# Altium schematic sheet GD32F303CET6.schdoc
size 127 x 101 mm
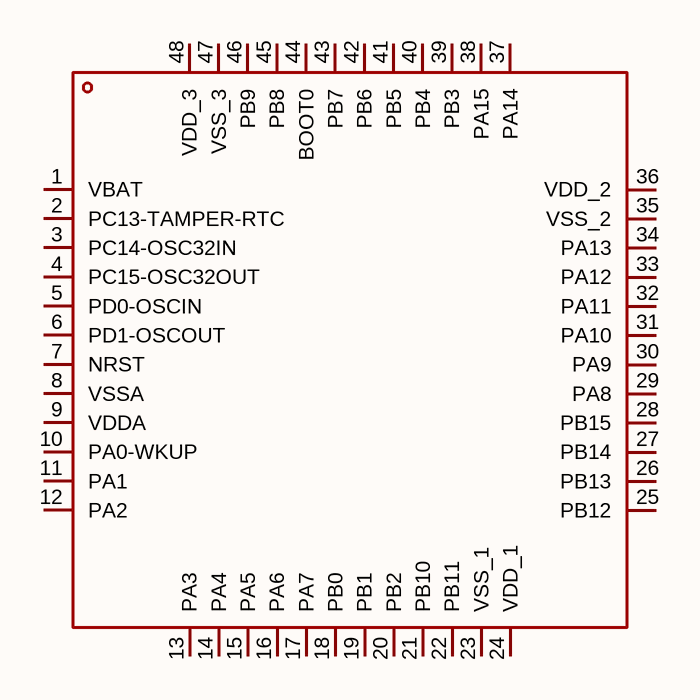
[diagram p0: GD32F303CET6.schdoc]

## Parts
U?  gd32f303cet6_c2826367  [LQFP-48_L7.0-W7.0-P0.50-LS9.0-BL]  (value not drawn)

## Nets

Not connected (* = marked no-connect by the designer): U? 1(VBAT) 2(PC13-TAMPER-RTC) 3(PC14-OSC32IN) 4(PC15-OSC32OUT) 5(PD0-OSCIN) 6(PD1-OSCOUT) 7(NRST) 8(VSSA) 9(VDDA) 10(PA0-WKUP) 11(PA1) 12(PA2) 13(PA3) 14(PA4) 15(PA5) 16(PA6) 17(PA7) 18(PB0) 19(PB1) 20(PB2) 21(PB10) 22(PB11) 23(VSS_1) 24(VDD_1) 25(PB12) 26(PB13) 27(PB14) 28(PB15) 29(PA8) 30(PA9) 31(PA10) 32(PA11) 33(PA12) 34(PA13) 35(VSS_2) 36(VDD_2) 37(PA14) 38(PA15) 39(PB3) 40(PB4) 41(PB5) 42(PB6) 43(PB7) 44(BOOT0) 45(PB8) 46(PB9) 47(VSS_3) 48(VDD_3)

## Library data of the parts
U? = gd32f303cet6_c2826367: CPU内核:ARM Cortex-M4;CPU最大主频:120MHz;; Manufacturer: GigaDevice(兆易创新); AddInBom: yes; ModelId: 093be70396ff421eb2cdb946d5311efc; ModelName: LQFP-48_L7.0-W7.0-H1.4-LS9.0-P0.50; ModelTransform: 354.331,354.331,0,0,0,0,0,0,0; CPU Maximum Speed: 120MHz; Program Storage Size: 512KB; Program Memory Type: FLASH; Number of I/O: 37; ADC (Bit): 12bit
